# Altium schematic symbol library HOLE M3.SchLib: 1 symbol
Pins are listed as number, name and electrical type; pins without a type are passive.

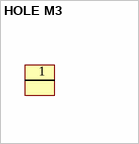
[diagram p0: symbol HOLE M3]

## HOLE M3
designator H?, comment NONE
HOLE M3; Manufacturer: Used in BOM report; SymbolVersion: 2014 - 10 - 22; SymbolCreator: A0412036; CompType: Used in some BOM reports.  Useful for finding later.; U/M: EA
footprint HOLE M3 (M3 X0.5 HOLE NO METAL)
pins: 1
